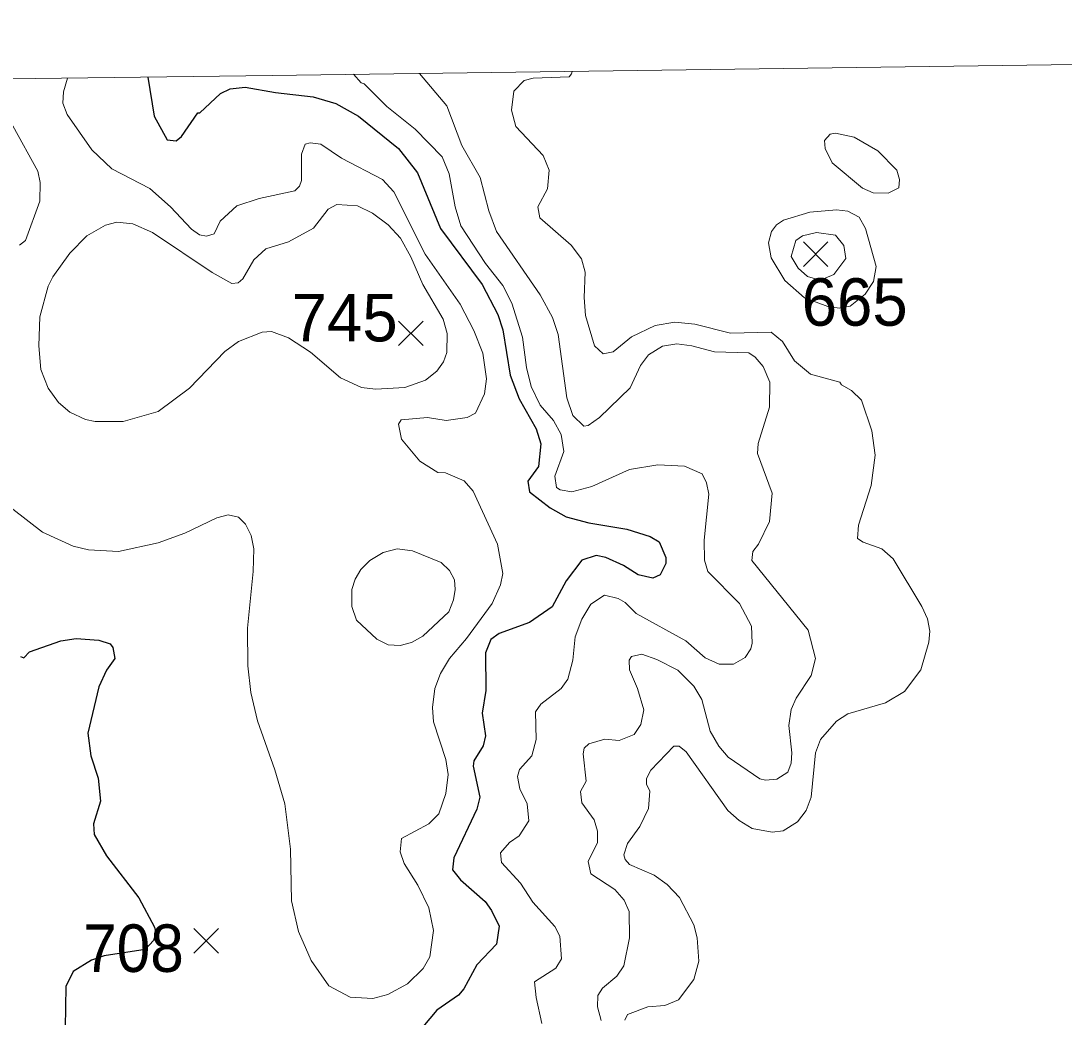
# Model space of a CAD drawing. Extents: x 265 to 291.4, y 7731.5 to 7759.6.
# Drawn here: x 267.199 to 268.956, y 7757.677 to 7759.355 of the extents above; entities that cross this region are included whole.
import ezdxf
from ezdxf.enums import TextEntityAlignment as Align

# ---------------------------------------------------------------- set-up
doc = ezdxf.new("R2010")
doc.units = 0
doc.header["$LTSCALE"] = 0.032
for name, color, linetype, lineweight in [('1', 7, 'Continuous', 25), ('2', 7, 'Continuous', 13), ('21', 7, 'Continuous', 25), ('61', 7, 'Continuous', 13), ('63', 7, 'Continuous', 25)]:
    doc.layers.add(name, color=color, linetype=linetype, lineweight=lineweight)

msp = doc.modelspace()

# ---------------------------------------------------------------- linework, layer by layer
at = {"layer": '1'}
for points in [[(267.4125, 7759.2603), (267.4229, 7759.1943), (267.4452, 7759.1545), (267.4603, 7759.1529), (267.4691, 7759.1601), (267.4969, 7759.1999), (267.5001, 7759.1999), (267.5351, 7759.2325), (267.551, 7759.2404), (267.5765, 7759.2436), (267.6274, 7759.2341), (267.691, 7759.2269), (267.7292, 7759.2158), (267.7674, 7759.1943), (267.835, 7759.1402), (267.8668, 7759.0989), (267.9058, 7759.005), (267.9758, 7758.9111), (268.002, 7758.8602), (268.0108, 7758.8348), (268.0227, 7758.7584), (268.0378, 7758.7186), (268.0665, 7758.6677), (268.0744, 7758.6423), (268.0704, 7758.6041), (268.0529, 7758.5794), (268.0553, 7758.5619), (268.0903, 7758.5349), (268.1174, 7758.5197), (268.1556, 7758.5094), (268.2192, 7758.499), (268.259, 7758.4863), (268.2741, 7758.4776), (268.2852, 7758.4513), (268.2852, 7758.441), (268.2757, 7758.4219), (268.263, 7758.4163), (268.2383, 7758.4219), (268.2137, 7758.4378), (268.1842, 7758.4513), (268.1675, 7758.4545), (268.1436, 7758.4466), (268.1174, 7758.4116), (268.0935, 7758.3678), (268.0554, 7758.3415), (268.0044, 7758.3232), (267.9901, 7758.3129), (267.9814, 7758.2907), (267.9821, 7758.227), (267.9758, 7758.1888), (267.9814, 7758.1506), (267.9774, 7758.1339), (267.9615, 7758.1085), (267.9607, 7758.0997), (267.9718, 7758.0472), (267.967, 7758.0273), (267.928, 7757.9454), (267.9257, 7757.9247), (267.9392, 7757.908), (267.9806, 7757.8714), (267.9917, 7757.8563), (268.0044, 7757.83), (267.9997, 7757.7998), (267.967, 7757.7648), (267.9448, 7757.7243), (267.936, 7757.7139), (267.8994, 7757.6884), (267.8755, 7757.6606)], [(267.1978, 7758.2843), (267.2034, 7758.2819), (267.2129, 7758.2922), (267.2662, 7758.3105), (267.2917, 7758.3145), (267.3299, 7758.3121), (267.3489, 7758.3058), (267.3537, 7758.2994), (267.3569, 7758.2811), (267.3426, 7758.2612), (267.3299, 7758.2334), (267.3116, 7758.1554), (267.3163, 7758.1172), (267.3291, 7758.0791), (267.333, 7758.0409), (267.3211, 7758.0027), (267.3219, 7757.9844), (267.3426, 7757.9486), (267.3975, 7757.8778), (267.4237, 7757.8285), (267.426, 7757.818), (267.422, 7757.806), (267.4081, 7757.7908), (267.3392, 7757.7802), (267.3174, 7757.7729), (267.2869, 7757.7537), (267.2742, 7757.7282), (267.2734, 7757.659)]]:
    msp.add_lwpolyline(points, dxfattribs=at)
at = {"layer": '2'}
for points in [[(267.6679, 7759.0766), (267.66, 7759.0686), (267.6003, 7759.0559), (267.5622, 7759.0432), (267.5343, 7759.0177), (267.524, 7758.9962), (267.5112, 7758.9923), (267.4993, 7758.9946), (267.4858, 7759.0042), (267.4508, 7759.0416), (267.4158, 7759.0726), (267.3521, 7759.106), (267.3179, 7759.1378), (267.2766, 7759.1975), (267.2694, 7759.2166), (267.2702, 7759.2357), (267.2773, 7759.2585)], [(267.7588, 7759.265), (267.7721, 7759.2508), (267.7769, 7759.2492), (267.8151, 7759.211), (267.8628, 7759.1728), (267.9082, 7759.1259), (267.9201, 7759.0973), (267.9304, 7759.0416), (267.94, 7759.0098), (267.9814, 7758.9461), (268.0108, 7758.9095), (268.0259, 7758.8793), (268.0434, 7758.822), (268.0506, 7758.7711), (268.0585, 7758.7393), (268.0736, 7758.7075), (268.0959, 7758.682), (268.1086, 7758.6582), (268.1134, 7758.6295), (268.0983, 7758.5882), (268.1007, 7758.5691), (268.1071, 7758.5651), (268.1269, 7758.5619), (268.1604, 7758.5707), (268.224, 7758.5993), (268.2717, 7758.6072), (268.3163, 7758.6049), (268.3465, 7758.5921), (268.3537, 7758.577), (268.3576, 7758.5579), (268.3497, 7758.48), (268.3505, 7758.4466), (268.356, 7758.4275), (268.4093, 7758.3734), (268.4292, 7758.3352), (268.4308, 7758.3066), (268.4284, 7758.297), (268.4189, 7758.2827), (268.399, 7758.2716), (268.3751, 7758.2716), (268.3513, 7758.2819), (268.3187, 7758.3105), (268.2351, 7758.3567), (268.2168, 7758.375), (268.2049, 7758.3821), (268.1818, 7758.3877), (268.1588, 7758.3726), (268.1436, 7758.3471), (268.1325, 7758.3177), (268.1285, 7758.2779), (268.1198, 7758.2461), (268.1086, 7758.2302), (268.0744, 7758.2039), (268.0657, 7758.1912), (268.0665, 7758.1443), (268.0593, 7758.1172), (268.0386, 7758.0942), (268.0355, 7758.0822), (268.0394, 7758.0615), (268.0514, 7758.0361), (268.0545, 7758.0075), (268.0378, 7757.982), (268.0219, 7757.9709), (268.0068, 7757.9534), (268.0084, 7757.9375), (268.0402, 7757.9025), (268.0609, 7757.8706), (268.0983, 7757.8293), (268.1063, 7757.8134), (268.1094, 7757.7752), (268.0999, 7757.7593), (268.0641, 7757.7362), (268.0665, 7757.71), (268.076, 7757.6662)], [(268.1476, 7758.13), (268.1556, 7758.1371), (268.1826, 7758.1451), (268.2065, 7758.1427), (268.232, 7758.153), (268.2431, 7758.1697), (268.2479, 7758.1944), (268.2375, 7758.2302), (268.224, 7758.262), (268.2232, 7758.2779), (268.2272, 7758.2843), (268.2447, 7758.2883), (268.2701, 7758.2795), (268.3051, 7758.2612), (268.3322, 7758.2342), (268.3457, 7758.2119), (268.36, 7758.1586), (268.3743, 7758.1331), (268.3902, 7758.1148), (268.4436, 7758.0782), (268.4531, 7758.0759), (268.4722, 7758.0775), (268.4905, 7758.0894), (268.496, 7758.1045), (268.4976, 7758.122), (268.4921, 7758.1681), (268.496, 7758.1952), (268.5048, 7758.2143), (268.5302, 7758.2525), (268.5374, 7758.2811), (268.5247, 7758.3288), (268.43, 7758.4458), (268.4316, 7758.4609), (268.4412, 7758.4736), (268.4595, 7758.5118), (268.4642, 7758.5595), (268.4396, 7758.6263), (268.4404, 7758.643), (268.4595, 7758.7043), (268.4602, 7758.7465), (268.4491, 7758.7727), (268.4356, 7758.7886), (268.4252, 7758.7958), (268.3672, 7758.7974), (268.329, 7758.8077), (268.3035, 7758.8109), (268.2797, 7758.8069), (268.2558, 7758.7926), (268.2423, 7758.7743), (268.2248, 7758.7369), (268.1731, 7758.6868), (268.154, 7758.6733), (268.1468, 7758.6725), (268.1285, 7758.69), (268.1182, 7758.7202), (268.1039, 7758.8268), (268.0943, 7758.8554), (268.0736, 7758.8936), (267.9997, 7759.0002), (267.9869, 7759.0352), (267.9726, 7759.0909), (267.9416, 7759.145), (267.9161, 7759.2118), (267.8699, 7759.2665)], [(268.1275, 7759.2699), (268.126, 7759.2657), (268.122, 7759.261), (268.0617, 7759.2587), (268.0466, 7759.2548), (268.0291, 7759.2365), (268.0251, 7759.2047), (268.0323, 7759.1768), (268.0784, 7759.1283), (268.0888, 7759.1036), (268.0856, 7759.0718), (268.0697, 7759.0416), (268.0728, 7759.0233), (268.1254, 7758.9771), (268.1428, 7758.9541), (268.1492, 7758.9318), (268.1476, 7758.8889), (268.15, 7758.8586), (268.1651, 7758.8077), (268.1794, 7758.7942), (268.1962, 7758.7974), (268.2272, 7758.8228), (268.267, 7758.8419), (268.3004, 7758.8475), (268.3338, 7758.8443), (268.3942, 7758.8292), (268.4626, 7758.8308), (268.4817, 7758.8149), (268.5016, 7758.7823), (268.5287, 7758.76), (268.578, 7758.7465), (268.5812, 7758.7417), (268.5979, 7758.7321), (268.6146, 7758.7162), (268.6321, 7758.6645), (268.6376, 7758.6232), (268.6313, 7758.5723), (268.6098, 7758.5054), (268.6082, 7758.4832), (268.6177, 7758.4768), (268.6488, 7758.4657), (268.6679, 7758.4489), (268.7164, 7758.3686), (268.7259, 7758.3479), (268.7299, 7758.3272), (268.7283, 7758.3082), (268.7148, 7758.262), (268.687, 7758.2254), (268.6551, 7758.2063), (268.5915, 7758.188), (268.5724, 7758.1753), (268.5454, 7758.1443), (268.5374, 7758.122), (268.5302, 7758.0472), (268.5215, 7758.025), (268.5072, 7758.0059), (268.4825, 7757.9907), (268.4642, 7757.9884), (268.4308, 7757.9947), (268.4085, 7758.0082), (268.3894, 7758.025), (268.3194, 7758.1236), (268.3075, 7758.1331), (268.2988, 7758.1331), (268.2598, 7758.0926), (268.2526, 7758.079), (268.2526, 7758.0695), (268.2582, 7758.0576), (268.2558, 7758.0281), (268.2415, 7757.9979), (268.2208, 7757.9693), (268.2144, 7757.9502), (268.2168, 7757.9422), (268.224, 7757.9342), (268.2654, 7757.916), (268.2876, 7757.9001), (268.3083, 7757.8786), (268.3322, 7757.8325), (268.3377, 7757.8102), (268.3409, 7757.7712), (268.3322, 7757.7402), (268.3067, 7757.706), (268.2837, 7757.6964), (268.255, 7757.694), (268.2208, 7757.6813), (268.216, 7757.6717)], [(267.1851, 7759.1784), (267.2272, 7759.102), (267.2312, 7759.083), (267.2304, 7759.0511), (267.2065, 7758.9851), (267.1962, 7758.9771)], [(267.7388, 7759.1235), (267.7037, 7759.1474), (267.6862, 7759.1498), (267.6775, 7759.1474), (267.6711, 7759.1307), (267.6711, 7759.0861), (267.6679, 7759.0766)], [(267.1851, 7758.5325), (267.2352, 7758.4935), (267.2869, 7758.4704), (267.3124, 7758.4641), (267.3633, 7758.4609), (267.4301, 7758.476), (267.4747, 7758.4919), (267.5287, 7758.5181), (267.5478, 7758.5229), (267.5653, 7758.5189), (267.5773, 7758.507), (267.5868, 7758.4879), (267.5908, 7758.4657), (267.59, 7758.4275), (267.5804, 7758.332), (267.5812, 7758.2684), (267.586, 7758.2238), (267.5971, 7758.1761), (267.6266, 7758.0934), (267.6433, 7758.0361), (267.6528, 7757.9597), (267.6544, 7757.873), (267.6663, 7757.8213), (267.6878, 7757.772), (267.7173, 7757.7298), (267.7531, 7757.7107), (267.7913, 7757.7084), (267.8167, 7757.7147), (267.8501, 7757.733), (267.8764, 7757.7585), (267.8875, 7757.7784), (267.8939, 7757.8229), (267.8859, 7757.8611), (267.8676, 7757.8993), (267.8445, 7757.9359), (267.8374, 7757.955), (267.8398, 7757.978), (267.8859, 7758.0027), (267.9026, 7758.0194), (267.9145, 7758.0536), (267.9185, 7758.0854), (267.9145, 7758.1109), (267.8939, 7758.1745), (267.8923, 7758.1984), (267.8962, 7758.2302), (267.9058, 7758.2557), (267.9209, 7758.2811), (267.9495, 7758.3145), (267.9925, 7758.3734), (268.0068, 7758.4052), (268.0108, 7758.4243), (268.0013, 7758.4736), (267.9607, 7758.5627), (267.9456, 7758.5802), (267.9138, 7758.5937), (267.901, 7758.5945), (267.8708, 7758.6136), (267.8398, 7758.6502), (267.835, 7758.6757), (267.839, 7758.6828), (267.8835, 7758.6868), (267.9153, 7758.682), (267.9504, 7758.6868), (267.9647, 7758.694), (267.9798, 7758.7266), (267.983, 7758.752), (267.9766, 7758.795), (267.9615, 7758.8332), (267.9384, 7758.8777), (267.8795, 7758.962), (267.827, 7759.067), (267.808, 7759.0877), (267.7388, 7759.1235)], [(268.1699, 7757.99), (268.1643, 7758.0091), (268.1436, 7758.0377), (268.1413, 7758.0568), (268.1508, 7758.0743), (268.146, 7758.1204), (268.1476, 7758.13)], [(268.1763, 7757.671), (268.1699, 7757.694), (268.1707, 7757.7131), (268.1787, 7757.7259), (268.2025, 7757.7457), (268.2144, 7757.7632), (268.224, 7757.8102), (268.2232, 7757.8547), (268.2152, 7757.8738), (268.1993, 7757.8921), (268.1587, 7757.9184), (268.154, 7757.939), (268.1699, 7757.9709), (268.1699, 7757.99)]]:
    msp.add_lwpolyline(points, dxfattribs=at)
for points in [[(268.5652, 7759.1156), (268.5533, 7759.1402), (268.5525, 7759.1537), (268.5621, 7759.1641), (268.5708, 7759.1657), (268.6026, 7759.1593), (268.6424, 7759.1362), (268.6742, 7759.1036), (268.679, 7759.0877), (268.6774, 7759.0736), (268.6599, 7759.0646), (268.6345, 7759.0654), (268.6162, 7759.0734)], [(267.6494, 7758.8212), (267.6865, 7758.7967), (267.7372, 7758.7536), (267.7722, 7758.7377), (267.796, 7758.7345), (267.8453, 7758.7377), (267.8803, 7758.7496), (267.8994, 7758.7647), (267.9106, 7758.7807), (267.9161, 7758.7966), (267.9169, 7758.8284), (267.9098, 7758.8523), (267.8756, 7758.9111), (267.8557, 7758.9573), (267.8382, 7758.9891), (267.8175, 7759.0114), (267.7912, 7759.0312), (267.7658, 7759.0432), (267.7308, 7759.0456), (267.7165, 7759.0376), (267.6918, 7759.0058), (267.6497, 7758.9827), (267.6115, 7758.9708), (267.5908, 7758.9525), (267.5725, 7758.9207), (267.5645, 7758.9135), (267.5542, 7758.9127), (267.5208, 7758.931), (267.4206, 7758.9986), (267.3871, 7759.0129), (267.3601, 7759.0161), (267.341, 7759.0106), (267.31, 7758.993), (267.2813, 7758.9636), (267.2527, 7758.9239), (267.2447, 7758.9079), (267.2304, 7758.8562), (267.2288, 7758.8077), (267.232, 7758.7679), (267.2447, 7758.7361), (267.2622, 7758.7123), (267.2813, 7758.6956), (267.3076, 7758.6836), (267.3235, 7758.6804), (267.3712, 7758.6804), (267.4301, 7758.6971), (267.4826, 7758.7361), (267.5423, 7758.7982), (267.5653, 7758.8149), (267.6051, 7758.8308), (267.621, 7758.8316)], [(268.621, 7758.8945), (268.5955, 7758.8743), (268.5776, 7758.871), (268.5583, 7758.8736), (268.5186, 7758.8882), (268.4857, 7758.9175), (268.4626, 7758.9557), (268.4579, 7758.9811), (268.4634, 7759.0002), (268.4714, 7759.0114), (268.4833, 7759.0193), (268.5279, 7759.0328), (268.5724, 7759.0368), (268.5915, 7759.0344), (268.6106, 7759.0241), (268.6217, 7759.005), (268.6392, 7758.9414), (268.6352, 7758.9159)], [(268.5883, 7758.9549), (268.5851, 7758.9764), (268.5708, 7758.9939), (268.539, 7758.9986), (268.5151, 7758.9931), (268.504, 7758.9851), (268.496, 7758.9581), (268.508, 7758.9382), (268.5239, 7758.9246), (268.5374, 7758.9207), (268.5533, 7758.9215), (268.5684, 7758.9278)], [(267.9066, 7758.4426), (267.9209, 7758.4291), (267.9289, 7758.4132), (267.9304, 7758.3972), (267.9273, 7758.3797), (267.9193, 7758.3598), (267.8756, 7758.3185), (267.8565, 7758.3081), (267.8374, 7758.3026), (267.8175, 7758.3042), (267.7984, 7758.3137), (267.7642, 7758.3455), (267.7562, 7758.3686), (267.7562, 7758.3972), (267.7618, 7758.4147), (267.7714, 7758.4307), (267.7865, 7758.4458), (267.8088, 7758.4593), (267.8326, 7758.4656), (267.8581, 7758.4625)]]:
    msp.add_lwpolyline(points, close=True, dxfattribs=at)
at = {"layer": '21'}
for p, q in [((268.5171, 7758.9827), (268.5583, 7758.9415)), ((268.5583, 7758.9827), (268.5171, 7758.9415)), ((267.8349, 7758.8492), (267.8761, 7758.808)), ((267.8761, 7758.8492), (267.8349, 7758.808)), ((267.4902, 7757.826), (267.5314, 7757.7848)), ((267.5314, 7757.826), (267.4902, 7757.7848))]:
    msp.add_line(p, q, dxfattribs=at)
at = {"layer": '63', "lineweight": 13}
msp.add_lwpolyline([(274.5533, 7759.355), (274.0201, 7759.348), (273.4869, 7759.341), (272.9538, 7759.334), (272.4206, 7759.327), (271.8874, 7759.32), (271.3543, 7759.3129), (270.8211, 7759.3059), (270.2879, 7759.2988), (269.7547, 7759.2917), (269.2216, 7759.2846), (268.6884, 7759.2775), (268.1552, 7759.2703), (267.622, 7759.2632), (267.0888, 7759.256), (266.5557, 7759.2488), (266.0225, 7759.2416), (265.4893, 7759.2344), (264.9561, 7759.2271)], dxfattribs=at)

# ---------------------------------------------------------------- texts
at = {"layer": '61'}
for s, p in [('665', (268.6033, 7758.8415)), ('745', (267.7441, 7758.8151))]:
    msp.add_text(s, height=0.08, dxfattribs=at).set_placement(p, align=Align.CENTER)
at = {"layer": '61', "width": 0.95}
msp.add_text('708', height=0.08, dxfattribs=at).set_placement((267.3883, 7757.753), align=Align.CENTER)

doc.saveas('drawing.dxf')
